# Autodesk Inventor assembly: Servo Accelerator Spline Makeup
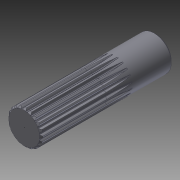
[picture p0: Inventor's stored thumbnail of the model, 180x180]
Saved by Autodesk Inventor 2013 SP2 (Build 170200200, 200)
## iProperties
Created: 2020-02
Part Number: Servo Accelerator Spline Makeup
Document SubType Name: Assembly
Designer: DELL
Author: DELL
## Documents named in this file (3)
- C:\Users\DELL\Dropbox\Inventor\Projects\Quadcopter F450\Assemblies\Servo - Design Accelerator Spline Tutorial\Design Accelerator - 5mm Shaft and Spline.iam
- C:\Users\DELL\Dropbox\Inventor\Projects\Quadcopter F450\Assemblies\Servo - Design Accelerator Spline Tutorial\Design Accelerator - 5mm Shaft and Spline\Design Accelerator\Shaft1.iam
- C:\Users\DELL\Dropbox\Inventor\Projects\Quadcopter F450\Assemblies\Servo - Design Accelerator Spline Tutorial\Design Accelerator - 5mm Shaft and Spline\Design Accelerator\Involute Spline Connection1.iam
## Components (2 placed, 2 different names)
1. Shaft:1 [sub-assembly] — Mate:1, Mate:2, Angle:1
2. Involute Spline Connection:1 [sub-assembly]
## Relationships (3: Mate 2, Angle 1)
- Mate:1: Shaft:1
- Mate:2: Shaft:1
- Angle:1: Shaft:1
